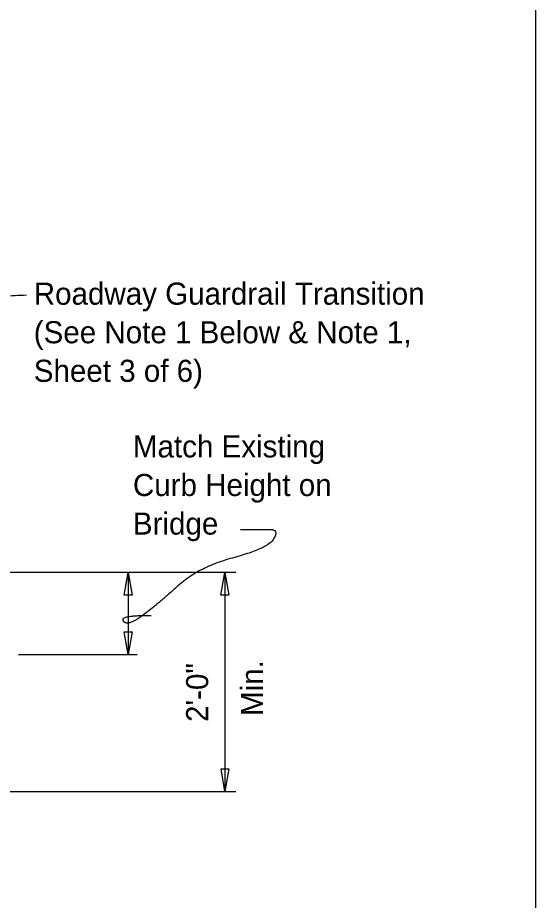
# Model space of a CAD drawing. Extents: x 1.5 to 68.7, y 0 to 31.1.
# Drawn here: x 37.81 to 42.53, y 8.74 to 16.79 of the extents above; entities that cross this region are included whole.
import ezdxf

# ---------------------------------------------------------------- set-up
doc = ezdxf.new("R2010")
doc.units = 0
for name, color, linetype in [('ActivePts-ConstElements', 7, 'Continuous'), ('AdhocPoint_dp', 7, 'Continuous'), ('SheetBorder_dp', 7, 'Continuous')]:
    doc.layers.add(name, color=color, linetype=linetype)

# ---------------------------------------------------------------- blocks, each defined once
blk = doc.blocks.new('Terminator-Arrow')
at = {"layer": 'AdhocPoint_dp'}
blk.add_lwpolyline([(0, 0), (-0.00041, 0.000069), (-0.00041, -0.000069)], close=True, dxfattribs=at)

msp = doc.modelspace()

# ---------------------------------------------------------------- linework, layer by layer
at = {"layer": 'ActivePts-ConstElements'}
msp.add_lwpolyline([(1.4667, 28.1828), (42.5333, 28.1828), (42.5333, 1.7828), (1.4667, 1.7828)], close=True, dxfattribs=at)
at = {"layer": 'AdhocPoint_dp'}
for p, q in [((36.8263, 11.7345), (39.8006, 11.7345)), ((38.8187, 11.7345), (38.8187, 10.9845)), ((39.7009, 11.7346), (39.7009, 9.7345)), ((37.8188, 10.9845), (38.9014, 10.9845)), ((36.8263, 9.7345), (39.8006, 9.7345))]:
    msp.add_line(p, q, dxfattribs=at)
for points in [[(37.8896, 14.2621), (37.3828, 14.2426), (37.3496, 14.1481), (37.4003, 13.5697)], [(39.8438, 12.1246), (40.0362, 12.1246), (40.1965, 12.1246), (40.0939, 11.9514), (39.4654, 11.7846), (39.0742, 11.4317), (38.8561, 11.2713), (38.7727, 11.2713), (38.7727, 11.3419), (39.0293, 11.3419)]]:
    msp.add_open_spline(points, degree=2, dxfattribs=at)

# ---------------------------------------------------------------- block references
at = {"layer": 'AdhocPoint_dp', "xscale": 506.349, "yscale": -512.1577380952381}
for p, rotation in [((38.8184, 11.7339), 90), ((39.7, 11.734), 90), ((38.8184, 10.984), -90), ((39.7007, 9.7344), -90)]:
    msp.add_blockref('Terminator-Arrow', p, dxfattribs=dict(at, rotation=rotation))

# ---------------------------------------------------------------- texts
at = {"layer": 'AdhocPoint_dp'}
for s, p in [('Roadway Guardrail Transition', (37.957, 14.1758)), ('(See Note 1 Below & Note 1,', (37.957, 13.8238)), ('Sheet 3 of 6)', (37.957, 13.4718)), ('Match Existing ', (38.8616, 12.7823)), ('Curb Height on', (38.8616, 12.4303)), ('Bridge', (38.8616, 12.0783))]:
    msp.add_text(s, height=0.2016, dxfattribs=at).set_placement(p)
at = {"layer": 'SheetBorder_dp'}
for s, p in [('2\'-0"', (39.5485, 10.3694)), ('Min.', (40.0489, 10.4239))]:
    msp.add_text(s, height=0.2016, rotation=90, dxfattribs=at).set_placement(p)

doc.saveas('drawing.dxf')
